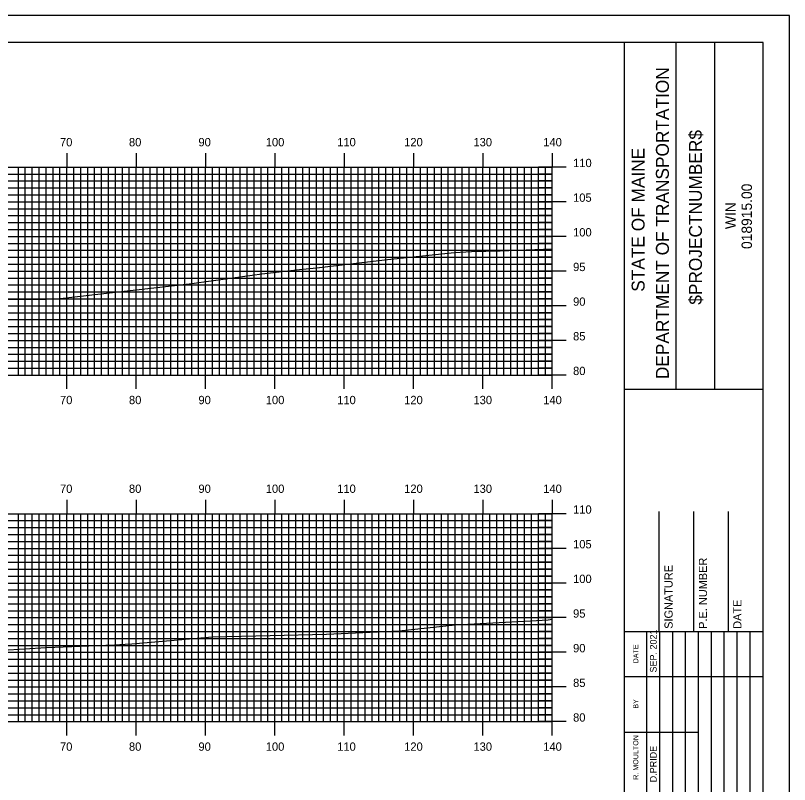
# Model space of a CAD drawing. Extents: x 1762578 to 1762921, y 442591 to 442811.
# Drawn here: x 1762806.4 to 1762918, y 442699.6 to 442810.5 of the extents above; entities that cross this region are included whole.
import ezdxf

# ---------------------------------------------------------------- set-up
doc = ezdxf.new("R2010")
doc.units = 0
for name, color, linetype in [('BORDER', 7, 'Continuous'), ('H_V ANNOTATION', 7, 'Continuous'), ('MAJOR', 7, 'Continuous'), ('MINOR', 7, 'Continuous'), ('PLOT BOUNDARY', 7, 'Continuous'), ('S_Roadway_Centerline', 7, 'Continuous')]:
    doc.layers.add(name, color=color, linetype=linetype)

msp = doc.modelspace()

# ---------------------------------------------------------------- linework, layer by layer
at = {"layer": 'BORDER'}
for p, q in [((1762894.18, 442596.67), (1762894.18, 442806.67)), ((1762901.64, 442756.66), (1762901.64, 442806.66)), ((1762907.23, 442756.66), (1762907.23, 442806.66)), ((1762894.18, 442756.65), (1762914.18, 442756.65)), ((1762899.18, 442721.67), (1762899.18, 442738.97)), ((1762904.18, 442721.67), (1762904.18, 442738.97)), ((1762909.18, 442721.67), (1762909.18, 442738.97)), ((1762894.18, 442721.67), (1762914.18, 442721.67))]:
    msp.add_line(p, q, dxfattribs=at)
msp.add_lwpolyline([(1762594.18, 442596.67), (1762914.18, 442596.67), (1762914.18, 442806.67), (1762594.18, 442806.67)], close=True, dxfattribs=at)
for points in [[(1762897.41, 442715.17), (1762897.41, 442721.67)], [(1762899.27, 442686.68), (1762899.27, 442721.67)], [(1762901.14, 442721.67), (1762901.14, 442686.68)], [(1762903, 442686.68), (1762903, 442721.67)], [(1762904.86, 442686.68), (1762904.86, 442721.67)], [(1762906.73, 442686.68), (1762906.73, 442721.67)], [(1762908.59, 442686.68), (1762908.59, 442721.67)], [(1762910.45, 442686.68), (1762910.45, 442721.67)], [(1762912.32, 442686.68), (1762912.32, 442721.67)], [(1762897.41, 442686.68), (1762897.41, 442720.26)], [(1762894.18, 442715.17), (1762914.18, 442715.17)], [(1762894.18, 442707.17), (1762897.41, 442707.17)], [(1762897.41, 442707.17), (1762904.86, 442707.17)]]:
    msp.add_lwpolyline(points, dxfattribs=at)
at = {"layer": 'MAJOR'}
for p, q in [((1762813.78, 442790.67), (1762813.78, 442788.67)), ((1762823.78, 442790.67), (1762823.78, 442788.67)), ((1762833.78, 442790.67), (1762833.78, 442788.67)), ((1762843.78, 442790.67), (1762843.78, 442788.67)), ((1762853.78, 442790.67), (1762853.78, 442788.67)), ((1762863.78, 442790.67), (1762863.78, 442788.67)), ((1762873.78, 442790.67), (1762873.78, 442788.67)), ((1762883.78, 442790.67), (1762883.78, 442788.67)), ((1762603.78, 442788.67), (1762883.78, 442788.67)), ((1762603.78, 442788.67), (1762883.78, 442788.67)), ((1762813.78, 442758.67), (1762813.78, 442788.67)), ((1762823.78, 442758.67), (1762823.78, 442788.67)), ((1762833.78, 442758.67), (1762833.78, 442788.67)), ((1762843.78, 442758.67), (1762843.78, 442788.67)), ((1762853.78, 442758.67), (1762853.78, 442788.67)), ((1762863.78, 442758.67), (1762863.78, 442788.67)), ((1762873.78, 442758.67), (1762873.78, 442788.67)), ((1762885.78, 442788.67), (1762881.78, 442788.67)), ((1762883.78, 442758.67), (1762883.78, 442788.67)), ((1762883.78, 442758.67), (1762883.78, 442788.67)), ((1762603.78, 442783.67), (1762883.78, 442783.67)), ((1762885.78, 442783.67), (1762881.78, 442783.67)), ((1762603.78, 442778.67), (1762883.78, 442778.67)), ((1762885.78, 442778.67), (1762881.78, 442778.67)), ((1762603.78, 442773.67), (1762883.78, 442773.67)), ((1762885.78, 442773.67), (1762881.78, 442773.67)), ((1762603.78, 442768.67), (1762883.78, 442768.67)), ((1762885.78, 442768.67), (1762881.78, 442768.67)), ((1762603.78, 442763.67), (1762883.78, 442763.67)), ((1762885.78, 442763.67), (1762881.78, 442763.67)), ((1762603.78, 442758.67), (1762883.78, 442758.67)), ((1762603.78, 442758.67), (1762883.78, 442758.67)), ((1762813.78, 442756.66), (1762813.78, 442758.67)), ((1762823.78, 442756.66), (1762823.78, 442758.67)), ((1762833.78, 442756.66), (1762833.78, 442758.67)), ((1762843.78, 442756.66), (1762843.78, 442758.67)), ((1762853.78, 442756.66), (1762853.78, 442758.67)), ((1762863.78, 442756.66), (1762863.78, 442758.67)), ((1762873.78, 442756.66), (1762873.78, 442758.67)), ((1762885.78, 442758.67), (1762881.78, 442758.67)), ((1762883.78, 442756.66), (1762883.78, 442758.67)), ((1762813.78, 442740.67), (1762813.78, 442738.67)), ((1762823.78, 442740.67), (1762823.78, 442738.67)), ((1762833.78, 442740.67), (1762833.78, 442738.67)), ((1762843.78, 442740.67), (1762843.78, 442738.67)), ((1762853.78, 442740.67), (1762853.78, 442738.67)), ((1762863.78, 442740.67), (1762863.78, 442738.67)), ((1762873.78, 442740.67), (1762873.78, 442738.67)), ((1762883.78, 442740.67), (1762883.78, 442738.67)), ((1762603.78, 442738.67), (1762883.78, 442738.67)), ((1762603.78, 442738.67), (1762883.78, 442738.67)), ((1762813.78, 442708.67), (1762813.78, 442738.67)), ((1762823.78, 442708.67), (1762823.78, 442738.67)), ((1762833.78, 442708.67), (1762833.78, 442738.67)), ((1762843.78, 442708.67), (1762843.78, 442738.67)), ((1762853.78, 442708.67), (1762853.78, 442738.67)), ((1762863.78, 442708.67), (1762863.78, 442738.67)), ((1762873.78, 442708.67), (1762873.78, 442738.67)), ((1762885.78, 442738.67), (1762881.78, 442738.67)), ((1762883.78, 442708.67), (1762883.78, 442738.67)), ((1762883.78, 442708.67), (1762883.78, 442738.67)), ((1762603.78, 442733.67), (1762883.78, 442733.67)), ((1762885.78, 442733.67), (1762881.78, 442733.67)), ((1762603.78, 442728.67), (1762883.78, 442728.67)), ((1762885.78, 442728.67), (1762881.78, 442728.67)), ((1762603.78, 442723.67), (1762883.78, 442723.67)), ((1762885.78, 442723.67), (1762881.78, 442723.67)), ((1762603.78, 442718.67), (1762883.78, 442718.67)), ((1762885.78, 442718.67), (1762881.78, 442718.67)), ((1762603.78, 442713.67), (1762883.78, 442713.67)), ((1762885.78, 442713.67), (1762881.78, 442713.67)), ((1762603.78, 442708.67), (1762883.78, 442708.67)), ((1762603.78, 442708.67), (1762883.78, 442708.67)), ((1762813.78, 442706.66), (1762813.78, 442708.67)), ((1762823.78, 442706.66), (1762823.78, 442708.67)), ((1762833.78, 442706.66), (1762833.78, 442708.67)), ((1762843.78, 442706.66), (1762843.78, 442708.67)), ((1762853.78, 442706.66), (1762853.78, 442708.67)), ((1762863.78, 442706.66), (1762863.78, 442708.67)), ((1762873.78, 442706.66), (1762873.78, 442708.67)), ((1762885.78, 442708.67), (1762881.78, 442708.67)), ((1762883.78, 442706.66), (1762883.78, 442708.67))]:
    msp.add_line(p, q, dxfattribs=at)
at = {"layer": 'MINOR'}
for p, q in [((1762806.78, 442758.67), (1762806.78, 442788.67)), ((1762807.78, 442758.67), (1762807.78, 442788.67)), ((1762808.78, 442758.67), (1762808.78, 442788.67)), ((1762809.78, 442758.67), (1762809.78, 442788.67)), ((1762810.78, 442758.67), (1762810.78, 442788.67)), ((1762811.78, 442758.67), (1762811.78, 442788.67)), ((1762812.78, 442758.67), (1762812.78, 442788.67)), ((1762814.78, 442758.67), (1762814.78, 442788.67)), ((1762815.78, 442758.67), (1762815.78, 442788.67)), ((1762816.78, 442758.67), (1762816.78, 442788.67)), ((1762817.78, 442758.67), (1762817.78, 442788.67)), ((1762818.78, 442758.67), (1762818.78, 442788.67)), ((1762819.78, 442758.67), (1762819.78, 442788.67)), ((1762820.78, 442758.67), (1762820.78, 442788.67)), ((1762821.78, 442758.67), (1762821.78, 442788.67)), ((1762822.78, 442758.67), (1762822.78, 442788.67)), ((1762824.78, 442758.67), (1762824.78, 442788.67)), ((1762825.78, 442758.67), (1762825.78, 442788.67)), ((1762826.78, 442758.67), (1762826.78, 442788.67)), ((1762827.78, 442758.67), (1762827.78, 442788.67)), ((1762828.78, 442758.67), (1762828.78, 442788.67)), ((1762829.78, 442758.67), (1762829.78, 442788.67)), ((1762830.78, 442758.67), (1762830.78, 442788.67)), ((1762831.78, 442758.67), (1762831.78, 442788.67)), ((1762832.78, 442758.67), (1762832.78, 442788.67)), ((1762834.78, 442758.67), (1762834.78, 442788.67)), ((1762835.78, 442758.67), (1762835.78, 442788.67)), ((1762836.78, 442758.67), (1762836.78, 442788.67)), ((1762837.78, 442758.67), (1762837.78, 442788.67)), ((1762838.78, 442758.67), (1762838.78, 442788.67)), ((1762839.78, 442758.67), (1762839.78, 442788.67)), ((1762840.78, 442758.67), (1762840.78, 442788.67)), ((1762841.78, 442758.67), (1762841.78, 442788.67)), ((1762842.78, 442758.67), (1762842.78, 442788.67)), ((1762844.78, 442758.67), (1762844.78, 442788.67)), ((1762845.78, 442758.67), (1762845.78, 442788.67)), ((1762846.78, 442758.67), (1762846.78, 442788.67)), ((1762847.78, 442758.67), (1762847.78, 442788.67)), ((1762848.78, 442758.67), (1762848.78, 442788.67)), ((1762849.78, 442758.67), (1762849.78, 442788.67)), ((1762850.78, 442758.67), (1762850.78, 442788.67)), ((1762851.78, 442758.67), (1762851.78, 442788.67)), ((1762852.78, 442758.67), (1762852.78, 442788.67)), ((1762854.78, 442758.67), (1762854.78, 442788.67)), ((1762855.78, 442758.67), (1762855.78, 442788.67)), ((1762856.78, 442758.67), (1762856.78, 442788.67)), ((1762857.78, 442758.67), (1762857.78, 442788.67)), ((1762858.78, 442758.67), (1762858.78, 442788.67)), ((1762859.78, 442758.67), (1762859.78, 442788.67)), ((1762860.78, 442758.67), (1762860.78, 442788.67)), ((1762861.78, 442758.67), (1762861.78, 442788.67)), ((1762862.78, 442758.67), (1762862.78, 442788.67)), ((1762864.78, 442758.67), (1762864.78, 442788.67)), ((1762865.78, 442758.67), (1762865.78, 442788.67)), ((1762866.78, 442758.67), (1762866.78, 442788.67)), ((1762867.78, 442758.67), (1762867.78, 442788.67)), ((1762868.78, 442758.67), (1762868.78, 442788.67)), ((1762869.78, 442758.67), (1762869.78, 442788.67)), ((1762870.78, 442758.67), (1762870.78, 442788.67)), ((1762871.78, 442758.67), (1762871.78, 442788.67)), ((1762872.78, 442758.67), (1762872.78, 442788.67)), ((1762874.78, 442758.67), (1762874.78, 442788.67)), ((1762875.78, 442758.67), (1762875.78, 442788.67)), ((1762876.78, 442758.67), (1762876.78, 442788.67)), ((1762877.78, 442758.67), (1762877.78, 442788.67)), ((1762878.78, 442758.67), (1762878.78, 442788.67)), ((1762879.78, 442758.67), (1762879.78, 442788.67)), ((1762880.78, 442758.67), (1762880.78, 442788.67)), ((1762881.78, 442758.67), (1762881.78, 442788.67)), ((1762882.78, 442758.67), (1762882.78, 442788.67)), ((1762603.78, 442787.67), (1762883.78, 442787.67)), ((1762603.78, 442786.67), (1762883.78, 442786.67)), ((1762883.78, 442787.67), (1762881.78, 442787.67)), ((1762883.78, 442786.67), (1762881.78, 442786.67)), ((1762603.78, 442785.67), (1762883.78, 442785.67)), ((1762883.78, 442785.67), (1762881.78, 442785.67)), ((1762603.78, 442784.67), (1762883.78, 442784.67)), ((1762883.78, 442784.67), (1762881.78, 442784.67)), ((1762603.78, 442782.67), (1762883.78, 442782.67)), ((1762883.78, 442782.67), (1762881.78, 442782.67)), ((1762603.78, 442781.67), (1762883.78, 442781.67)), ((1762883.78, 442781.67), (1762881.78, 442781.67)), ((1762603.78, 442780.67), (1762883.78, 442780.67)), ((1762883.78, 442780.67), (1762881.78, 442780.67)), ((1762603.78, 442779.67), (1762883.78, 442779.67)), ((1762883.78, 442779.67), (1762881.78, 442779.67)), ((1762603.78, 442777.67), (1762883.78, 442777.67)), ((1762603.78, 442776.67), (1762883.78, 442776.67)), ((1762883.78, 442777.67), (1762881.78, 442777.67)), ((1762883.78, 442776.67), (1762881.78, 442776.67)), ((1762603.78, 442775.67), (1762883.78, 442775.67)), ((1762883.78, 442775.67), (1762881.78, 442775.67)), ((1762603.78, 442774.67), (1762883.78, 442774.67)), ((1762883.78, 442774.67), (1762881.78, 442774.67)), ((1762603.78, 442772.67), (1762883.78, 442772.67)), ((1762883.78, 442772.67), (1762881.78, 442772.67)), ((1762603.78, 442771.67), (1762883.78, 442771.67)), ((1762883.78, 442771.67), (1762881.78, 442771.67)), ((1762603.78, 442770.67), (1762883.78, 442770.67)), ((1762883.78, 442770.67), (1762881.78, 442770.67)), ((1762603.78, 442769.67), (1762883.78, 442769.67)), ((1762883.78, 442769.67), (1762881.78, 442769.67)), ((1762603.78, 442767.67), (1762883.78, 442767.67)), ((1762883.78, 442767.67), (1762881.78, 442767.67)), ((1762603.78, 442766.67), (1762883.78, 442766.67)), ((1762883.78, 442766.67), (1762881.78, 442766.67)), ((1762603.78, 442765.67), (1762883.78, 442765.67)), ((1762883.78, 442765.67), (1762881.78, 442765.67)), ((1762603.78, 442764.67), (1762883.78, 442764.67)), ((1762883.78, 442764.67), (1762881.78, 442764.67)), ((1762603.78, 442762.67), (1762883.78, 442762.67)), ((1762883.78, 442762.67), (1762881.78, 442762.67)), ((1762603.78, 442761.67), (1762883.78, 442761.67)), ((1762883.78, 442761.67), (1762881.78, 442761.67)), ((1762603.78, 442760.67), (1762883.78, 442760.67)), ((1762883.78, 442760.67), (1762881.78, 442760.67)), ((1762603.78, 442759.67), (1762883.78, 442759.67)), ((1762883.78, 442759.67), (1762881.78, 442759.67)), ((1762806.78, 442708.67), (1762806.78, 442738.67)), ((1762807.78, 442708.67), (1762807.78, 442738.67)), ((1762808.78, 442708.67), (1762808.78, 442738.67)), ((1762809.78, 442708.67), (1762809.78, 442738.67)), ((1762810.78, 442708.67), (1762810.78, 442738.67)), ((1762811.78, 442708.67), (1762811.78, 442738.67)), ((1762812.78, 442708.67), (1762812.78, 442738.67)), ((1762814.78, 442708.67), (1762814.78, 442738.67)), ((1762815.78, 442708.67), (1762815.78, 442738.67)), ((1762816.78, 442708.67), (1762816.78, 442738.67)), ((1762817.78, 442708.67), (1762817.78, 442738.67)), ((1762818.78, 442708.67), (1762818.78, 442738.67)), ((1762819.78, 442708.67), (1762819.78, 442738.67)), ((1762820.78, 442708.67), (1762820.78, 442738.67)), ((1762821.78, 442708.67), (1762821.78, 442738.67)), ((1762822.78, 442708.67), (1762822.78, 442738.67)), ((1762824.78, 442708.67), (1762824.78, 442738.67)), ((1762825.78, 442708.67), (1762825.78, 442738.67)), ((1762826.78, 442708.67), (1762826.78, 442738.67)), ((1762827.78, 442708.67), (1762827.78, 442738.67)), ((1762828.78, 442708.67), (1762828.78, 442738.67)), ((1762829.78, 442708.67), (1762829.78, 442738.67)), ((1762830.78, 442708.67), (1762830.78, 442738.67)), ((1762831.78, 442708.67), (1762831.78, 442738.67)), ((1762832.78, 442708.67), (1762832.78, 442738.67)), ((1762834.78, 442708.67), (1762834.78, 442738.67)), ((1762835.78, 442708.67), (1762835.78, 442738.67)), ((1762836.78, 442708.67), (1762836.78, 442738.67)), ((1762837.78, 442708.67), (1762837.78, 442738.67)), ((1762838.78, 442708.67), (1762838.78, 442738.67)), ((1762839.78, 442708.67), (1762839.78, 442738.67)), ((1762840.78, 442708.67), (1762840.78, 442738.67)), ((1762841.78, 442708.67), (1762841.78, 442738.67)), ((1762842.78, 442708.67), (1762842.78, 442738.67)), ((1762844.78, 442708.67), (1762844.78, 442738.67)), ((1762845.78, 442708.67), (1762845.78, 442738.67)), ((1762846.78, 442708.67), (1762846.78, 442738.67)), ((1762847.78, 442708.67), (1762847.78, 442738.67)), ((1762848.78, 442708.67), (1762848.78, 442738.67)), ((1762849.78, 442708.67), (1762849.78, 442738.67)), ((1762850.78, 442708.67), (1762850.78, 442738.67)), ((1762851.78, 442708.67), (1762851.78, 442738.67)), ((1762852.78, 442708.67), (1762852.78, 442738.67)), ((1762854.78, 442708.67), (1762854.78, 442738.67)), ((1762855.78, 442708.67), (1762855.78, 442738.67)), ((1762856.78, 442708.67), (1762856.78, 442738.67)), ((1762857.78, 442708.67), (1762857.78, 442738.67)), ((1762858.78, 442708.67), (1762858.78, 442738.67)), ((1762859.78, 442708.67), (1762859.78, 442738.67)), ((1762860.78, 442708.67), (1762860.78, 442738.67)), ((1762861.78, 442708.67), (1762861.78, 442738.67)), ((1762862.78, 442708.67), (1762862.78, 442738.67)), ((1762864.78, 442708.67), (1762864.78, 442738.67)), ((1762865.78, 442708.67), (1762865.78, 442738.67)), ((1762866.78, 442708.67), (1762866.78, 442738.67)), ((1762867.78, 442708.67), (1762867.78, 442738.67)), ((1762868.78, 442708.67), (1762868.78, 442738.67)), ((1762869.78, 442708.67), (1762869.78, 442738.67)), ((1762870.78, 442708.67), (1762870.78, 442738.67)), ((1762871.78, 442708.67), (1762871.78, 442738.67)), ((1762872.78, 442708.67), (1762872.78, 442738.67)), ((1762874.78, 442708.67), (1762874.78, 442738.67)), ((1762875.78, 442708.67), (1762875.78, 442738.67)), ((1762876.78, 442708.67), (1762876.78, 442738.67)), ((1762877.78, 442708.67), (1762877.78, 442738.67)), ((1762878.78, 442708.67), (1762878.78, 442738.67)), ((1762879.78, 442708.67), (1762879.78, 442738.67)), ((1762880.78, 442708.67), (1762880.78, 442738.67)), ((1762881.78, 442708.67), (1762881.78, 442738.67)), ((1762882.78, 442708.67), (1762882.78, 442738.67)), ((1762603.78, 442737.67), (1762883.78, 442737.67)), ((1762883.78, 442737.67), (1762881.78, 442737.67)), ((1762603.78, 442736.67), (1762883.78, 442736.67)), ((1762883.78, 442736.67), (1762881.78, 442736.67)), ((1762603.78, 442735.67), (1762883.78, 442735.67)), ((1762883.78, 442735.67), (1762881.78, 442735.67)), ((1762603.78, 442734.67), (1762883.78, 442734.67)), ((1762883.78, 442734.67), (1762881.78, 442734.67)), ((1762603.78, 442732.67), (1762883.78, 442732.67)), ((1762883.78, 442732.67), (1762881.78, 442732.67)), ((1762603.78, 442731.67), (1762883.78, 442731.67)), ((1762883.78, 442731.67), (1762881.78, 442731.67)), ((1762603.78, 442730.67), (1762883.78, 442730.67)), ((1762883.78, 442730.67), (1762881.78, 442730.67)), ((1762603.78, 442729.67), (1762883.78, 442729.67)), ((1762883.78, 442729.67), (1762881.78, 442729.67)), ((1762603.78, 442727.67), (1762883.78, 442727.67)), ((1762883.78, 442727.67), (1762881.78, 442727.67)), ((1762603.78, 442726.67), (1762883.78, 442726.67)), ((1762883.78, 442726.67), (1762881.78, 442726.67)), ((1762603.78, 442725.67), (1762883.78, 442725.67)), ((1762883.78, 442725.67), (1762881.78, 442725.67)), ((1762603.78, 442724.67), (1762883.78, 442724.67)), ((1762883.78, 442724.67), (1762881.78, 442724.67)), ((1762603.78, 442722.67), (1762883.78, 442722.67)), ((1762883.78, 442722.67), (1762881.78, 442722.67)), ((1762603.78, 442721.67), (1762883.78, 442721.67)), ((1762883.78, 442721.67), (1762881.78, 442721.67)), ((1762603.78, 442720.67), (1762883.78, 442720.67)), ((1762603.78, 442719.67), (1762883.78, 442719.67)), ((1762883.78, 442720.67), (1762881.78, 442720.67)), ((1762883.78, 442719.67), (1762881.78, 442719.67)), ((1762603.78, 442717.67), (1762883.78, 442717.67)), ((1762883.78, 442717.67), (1762881.78, 442717.67)), ((1762603.78, 442716.67), (1762883.78, 442716.67)), ((1762883.78, 442716.67), (1762881.78, 442716.67)), ((1762603.78, 442715.67), (1762883.78, 442715.67)), ((1762883.78, 442715.67), (1762881.78, 442715.67)), ((1762603.78, 442714.67), (1762883.78, 442714.67)), ((1762883.78, 442714.67), (1762881.78, 442714.67)), ((1762603.78, 442712.67), (1762883.78, 442712.67)), ((1762883.78, 442712.67), (1762881.78, 442712.67)), ((1762603.78, 442711.67), (1762883.78, 442711.67)), ((1762883.78, 442711.67), (1762881.78, 442711.67)), ((1762603.78, 442710.67), (1762883.78, 442710.67)), ((1762603.78, 442709.67), (1762883.78, 442709.67)), ((1762883.78, 442710.67), (1762881.78, 442710.67)), ((1762883.78, 442709.67), (1762881.78, 442709.67))]:
    msp.add_line(p, q, dxfattribs=at)
at = {"layer": 'PLOT BOUNDARY'}
msp.add_lwpolyline([(1762577.99, 442590.55), (1762917.99, 442590.55), (1762917.99, 442810.55), (1762577.99, 442810.55)], close=True, dxfattribs=at)
at = {"layer": 'S_Roadway_Centerline'}
for points in [[(1762793.46, 442769.52), (1762808.18, 442769.62), (1762810.81, 442769.6), (1762812.4, 442769.66), (1762817.82, 442770.3), (1762831.4, 442771.81), (1762834.91, 442772.32), (1762841.91, 442773.29), (1762847.33, 442773.89), (1762849.77, 442774.13), (1762860.03, 442775.34), (1762869.69, 442776.37), (1762872.15, 442776.5), (1762876.24, 442776.61), (1762883.78, 442776.86)], [(1762804.53, 442719), (1762810.77, 442719.38), (1762820.62, 442719.75), (1762822.18, 442719.86), (1762823.15, 442719.89), (1762834.77, 442720.89), (1762843.1, 442721.1), (1762851.22, 442721.27), (1762861.7, 442721.78), (1762869.76, 442722.63), (1762880.66, 442723.19), (1762883.19, 442723.38), (1762883.78, 442723.43)]]:
    msp.add_lwpolyline(points, dxfattribs=at)

# ---------------------------------------------------------------- texts
at = {"layer": 'BORDER'}
for s, height, p in [('DEPARTMENT OF TRANSPORTATION', 1.8635, (1762900.59, 442758.08)), ('$PROJECTNUMBER$', 1.8635, (1762905.36, 442768.82)), ('STATE OF MAINE', 1.8635, (1762897.09, 442770.69)), ('018915.00', 1.491, (1762912.57, 442776.86)), ('WIN', 1.491, (1762910.25, 442779.73)), ('P.E. NUMBER', 1.1811, (1762906.1, 442722.06)), ('SIGNATURE', 1.181, (1762901.14, 442722.06)), ('DATE', 1.181, (1762911.06, 442722.06)), ('SEP. 2021', 0.969, (1762898.83, 442715.76)), ('DATE', 0.743, (1762896.19, 442717.08)), ('BY', 0.743, (1762896.19, 442710.54)), ('R. MOULTON', 0.745, (1762896.19, 442700.28)), ('D.PRIDE', 0.969, (1762898.83, 442699.92))]:
    msp.add_text(s, height=height, rotation=90, dxfattribs=at).set_placement(p)
at = {"layer": 'H_V ANNOTATION'}
for s, p in [('70', (1762812.78, 442791.67)), ('80', (1762822.73, 442791.67)), ('90', (1762832.75, 442791.67)), ('100', (1762842.46, 442791.67)), ('110', (1762852.76, 442791.67)), ('120', (1762862.42, 442791.67)), ('130', (1762872.41, 442791.67)), ('140', (1762882.48, 442791.67)), ('110', (1762886.78, 442788.67)), ('105', (1762886.78, 442783.67)), ('100', (1762886.78, 442778.67)), ('95', (1762886.78, 442773.67)), ('90', (1762886.78, 442768.67)), ('85', (1762886.78, 442763.67)), ('80', (1762886.78, 442758.67)), ('70', (1762812.78, 442754.47)), ('80', (1762822.73, 442754.47)), ('90', (1762832.75, 442754.47)), ('100', (1762842.46, 442754.47)), ('110', (1762852.76, 442754.47)), ('120', (1762862.42, 442754.47)), ('130', (1762872.41, 442754.47)), ('140', (1762882.48, 442754.47)), ('70', (1762812.78, 442741.67)), ('80', (1762822.73, 442741.67)), ('90', (1762832.75, 442741.67)), ('100', (1762842.46, 442741.67)), ('110', (1762852.76, 442741.67)), ('120', (1762862.42, 442741.67)), ('130', (1762872.41, 442741.67)), ('140', (1762882.48, 442741.67)), ('110', (1762886.78, 442738.67)), ('105', (1762886.78, 442733.67)), ('100', (1762886.78, 442728.67)), ('95', (1762886.78, 442723.67)), ('90', (1762886.78, 442718.67)), ('85', (1762886.78, 442713.67)), ('80', (1762886.78, 442708.67)), ('70', (1762812.78, 442704.47)), ('80', (1762822.73, 442704.47)), ('90', (1762832.75, 442704.47)), ('100', (1762842.46, 442704.47)), ('110', (1762852.76, 442704.47)), ('120', (1762862.42, 442704.47)), ('130', (1762872.41, 442704.47)), ('140', (1762882.48, 442704.47))]:
    msp.add_text(s, height=1.2, dxfattribs=at).set_placement(p)

doc.saveas('drawing.dxf')
